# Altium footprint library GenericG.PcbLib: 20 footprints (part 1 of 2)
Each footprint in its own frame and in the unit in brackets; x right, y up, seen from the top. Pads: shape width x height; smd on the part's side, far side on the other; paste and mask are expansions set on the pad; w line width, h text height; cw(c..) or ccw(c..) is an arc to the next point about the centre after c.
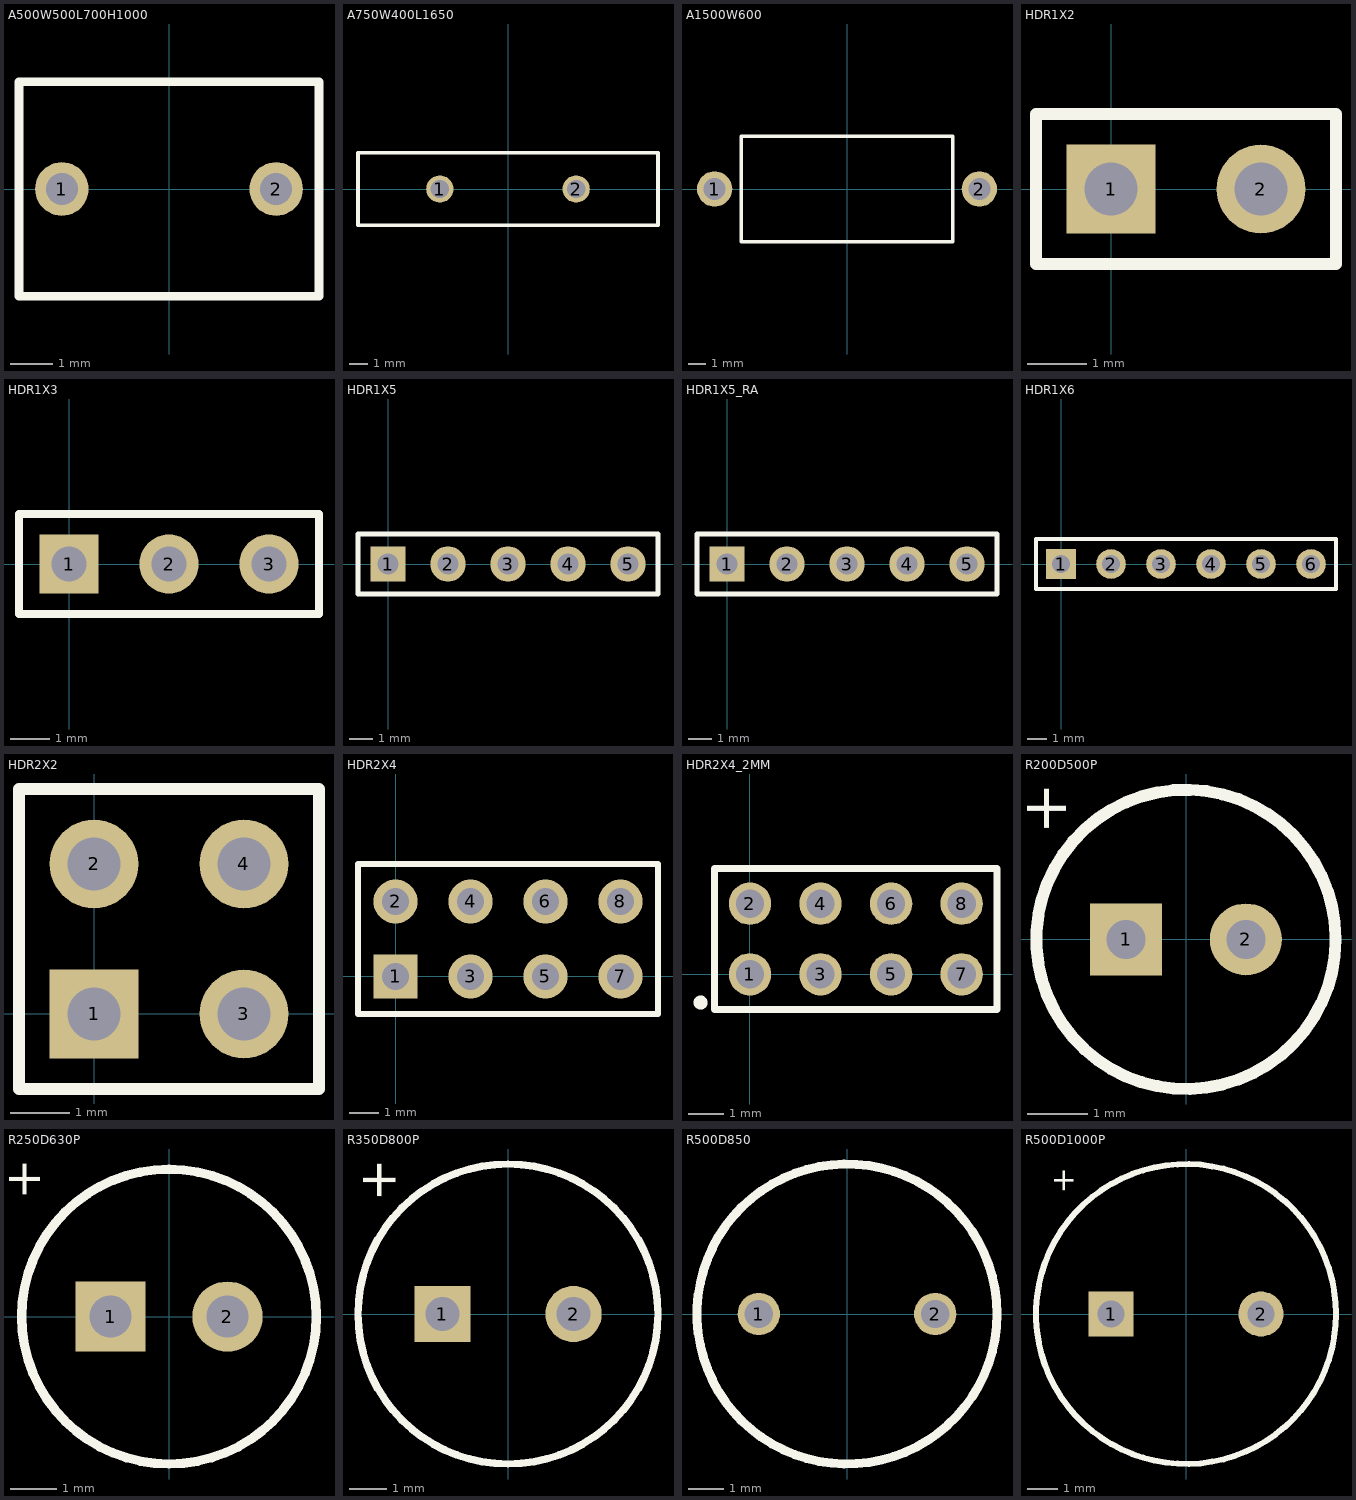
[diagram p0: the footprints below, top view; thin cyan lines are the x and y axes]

## A500W500L700H1000 [mm]
height 10
pads (2):
  round 1.25 hole 0.75: 1(-2.5,0) 2(2.5,0)
Top Overlay:
  lines w0.2: -3.5,-2.5 3.5,-2.5 3.5,2.5 -3.5,2.5 -3.5,-2.5
3D body: height 9.99, standoff 3.01, extent -3.472,-2.5 3.5,2.5

## A750W400L1650 [mm] "Axial, pitch 7.5mm 16.5mmx4mm"
pads (2):
  round 1.5 hole 1: 1(-3.75,0) 2(3.75,0)
Top Overlay:
  lines w0.2: -8.25,-2 -8.25,2 8.25,2 8.25,-2 -8.25,-2
3D body: height 19.98, standoff 3.52, extent -8.185,-2 8.25,2

## A1500W600 [mm] "Axial, 15mm x 6mm"
pads (2):
  round 2 hole 1.25: 1(-7.5,0) 2(7.5,0)
Top Overlay:
  lines w0.2: -6,-3 -6,3 6,3 6,-3 -6,-3
3D body: height 6.99, standoff 1.01, extent -6,-3 6,2.976

## HDR1X2 [mm] "Connector; Header; 2 Position"
pads (2):
  rect 1.5x1.5 hole 0.9: 1(0,0)
  round 1.5 hole 0.9: 2(2.54,0)
Top Overlay:
  lines w0.2: -1.27,-1.27 3.81,-1.27 3.81,1.27 -1.27,1.27 -1.27,-1.27
3D body: height 8.38, standoff -2.54, extent -1.27,-1.34 3.81,1.2

## HDR1X3 [mm] "Connector; Header; 3 Position"
pads (3):
  rect 1.5x1.5 hole 0.9: 1(0,0)
  round 1.5 hole 0.9: 2(2.54,0) 3(5.08,0)
Top Overlay:
  lines w0.2: -1.27,-1.27 -1.27,1.27 6.35,1.27 6.35,-1.27 -1.27,-1.27
3D body: height 8.38, standoff -2.54, extent -1.27,-1.27 6.35,1.27

## HDR1X5 [mm]
pads (5):
  rect 1.5x1.5 hole 0.9: 1(0,0)
  round 1.5 hole 0.9: 2(2.54,0) 3(5.08,0) 4(7.62,0) 5(10.16,0)
Top Overlay:
  lines w0.2: -1.27,-1.27 -1.27,1.27 11.43,1.27 11.43,-1.27 -1.27,-1.27
3D body: height 8.38, standoff -2.54, extent -1.35,-1.3 11.35,1.24

## HDR1X5_RA [mm]
pads (5):
  rect 1.5x1.5 hole 0.9: 1(0,0)
  round 1.5 hole 0.9: 2(2.54,0) 3(5.08,0) 4(7.62,0) 5(10.16,0)
Top Overlay:
  lines w0.2: -1.27,-1.27 11.43,-1.27 11.43,1.27 -1.27,1.27 -1.27,-1.27
3D body: height 2.54, standoff -3.53, extent -1.25,-8.22 11.45,0.4

## HDR1X6 [mm] "Connector; Header; 6 Position"
pads (6):
  rect 1.5x1.5 hole 0.9: 1(0,0)
  round 1.5 hole 0.9: 2(2.54,0) 3(5.08,0) 4(7.62,0) 5(10.16,0) 6(12.7,0)
Top Overlay:
  lines w0.2: -1.27,-1.27 13.97,-1.27 13.97,1.27 -1.27,1.27 -1.27,-1.27
3D body: height 8.38, standoff -2.54, extent -1.27,-1.27 13.97,1.27

## HDR2X2 [mm] "Connector; Header; 2x2 Position"
pads (4):
  rect 1.5x1.5 hole 0.9: 1(0,0)
  round 1.5 hole 0.9: 2(0,2.54) 3(2.54,0) 4(2.54,2.54)
Top Overlay:
  lines w0.2: -1.27,-1.27 -1.27,3.81 3.81,3.81 3.81,-1.27 -1.27,-1.27
3D body: height 8.38, standoff -2.54, extent -1.27,-1.27 3.81,3.81

## HDR2X4 [mm] "Connector; Header; 4x2 Position"
pads (8):
  rect 1.5x1.5 hole 0.9: 1(0,0)
  round 1.5 hole 0.9: 2(0,2.54) 3(2.54,0) 4(2.54,2.54) 5(5.08,0) 6(5.08,2.54) 7(7.62,0) 8(7.62,2.54)
Top Overlay:
  lines w0.2: -1.27,-1.27 8.89,-1.27 8.89,3.81 -1.27,3.81 -1.27,-1.27
3D body: height 8.38, standoff -2.54, extent -1.27,-1.27 8.89,3.81

## HDR2X4_2MM [mm]
pads (8):
  round 1.2 hole 0.8: 1(0,0) 2(0,2) 3(2,0) 4(2,2) 5(4,0) 6(4,2) 7(6,0) 8(6,2)
Top Overlay:
  circle w0.2: c-1.4,-0.8 r0.1
  lines w0.2: -1,-1 7,-1 7,3 -1,3 -1,-1

## R200D500P [mm] "Radial, 2mm lead spacing and 5mm diameter, polarized"
height 13
pads (2):
  rect 1.2x1.2 hole 0.65: 1(-1,0)
  round 1.2 hole 0.65: 2(1,0)
Top Overlay:
  circle w0.2: c0,0 r2.5
  text "+" at -2,1.75 h0.76
3D body: height 13, standoff 0, extent -2.48,-2.495 2.5,2.495

## R250D630P [mm] "Radial, 2.5mm lead spacing and 6.3mm diameter, polarized"
height 11.2
pads (2):
  rect 1.5x1.5 hole 0.9: 1(-1.25,0)
  round 1.5 hole 0.9: 2(1.25,0)
Top Overlay:
  circle w0.2: c0,0 r3.15
  text "+" at -2.75,2.5 h0.76
3D body: height 11.2, standoff 0, extent -3.125,-3.144 3.15,3.144

## R350D800P [mm] "Radial, 3.5mm lead spacing and 8mm diameter, polarized"
height 15
pads (2):
  rect 1.5x1.5 hole 0.9: 1(-1.75,0)
  round 1.5 hole 0.9: 2(1.75,0)
Top Overlay:
  circle w0.2: c0,0 r4
  text "+" at -3,3 h1
3D body: height 15, standoff 0, extent -3.968,-3.992 4,3.992

## R500D850 [mm]
height 12
pads (2):
  round 1.2 hole 0.8: 1(-2.5,0) 2(2.5,0)
Top Overlay:
  circle w0.254: c0,0 r4.25
3D body: height 12, standoff 0, extent -4.216,-4.241 4.25,4.242

## R500D1000P [mm] "Radial, 5mm lead spacing and 10mm diameter, polarized"
height 17
pads (2):
  rect 1.5x1.5 hole 0.9: 1(-2.5,0)
  round 1.5 hole 0.9: 2(2.5,0)
Top Overlay:
  circle w0.2: c0,0 r5
  text "+" at -3.75,4 h0.76
3D body: height 17, standoff 0, extent -4.961,-4.99 5,4.99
